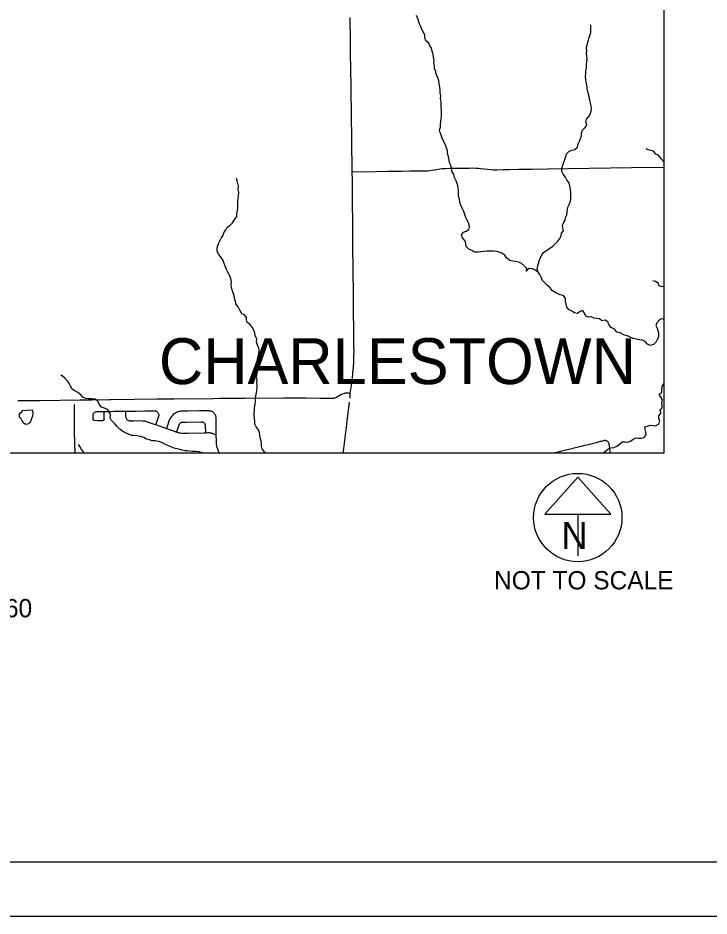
# Model space of a CAD drawing. Extents: x 0 to 34, y 0 to 22.
# Drawn here: x 12.67 to 19.09, y 0 to 8.34 of the extents above; entities that cross this region are included whole.
import ezdxf

# ---------------------------------------------------------------- set-up
doc = ezdxf.new("R2010")
doc.units = 0
for name, color, linetype in [('GM_X_County_Road', 7, 'Continuous'), ('GM_X_Minor_Lake', 7, 'Continuous'), ('GM_X_Minor_River', 7, 'Continuous'), ('GM_X_Township_Road', 7, 'Continuous'), ('GM_X_Township_Text', 7, 'Continuous'), ('SH_Border', 7, 'Continuous'), ('SH_Cut_Line', 7, 'Continuous'), ('SH_Masking', 7, 'Continuous'), ('SH_Text', 7, 'Continuous')]:
    doc.layers.add(name, color=color, linetype=linetype)

msp = doc.modelspace()

# ---------------------------------------------------------------- linework, layer by layer
at = {"layer": 'GM_X_County_Road'}
msp.add_lwpolyline([(15.6909, 4.2991), (15.6957, 4.3413), (15.7237, 4.5646), (15.727, 4.5955), (15.7482, 4.7727)], dxfattribs=at)
at = {"layer": 'GM_X_Minor_Lake'}
msp.add_line((12.805, 4.6981), (12.7056, 4.6922), dxfattribs=at)
msp.add_lwpolyline([(12.7056, 4.6922), (12.7048, 4.6799), (12.6917, 4.6693), (12.6794, 4.6663), (12.6785, 4.6606), (12.6797, 4.6368), (12.6912, 4.6256), (12.7047, 4.603), (12.7173, 4.5832), (12.7411, 4.5692), (12.76, 4.5713), (12.7807, 4.5839), (12.7899, 4.604), (12.801, 4.6288), (12.8084, 4.6497), (12.8092, 4.6602), (12.81, 4.6735), (12.806, 4.6905), (12.805, 4.6981)], dxfattribs=at)
at = {"layer": 'GM_X_Minor_River'}
msp.add_line((18.6636, 5.5436), (18.6712, 5.5421), dxfattribs=at)
for points in [[(16.7712, 6.6571), (16.7623, 6.6845), (16.7611, 6.712), (16.7607, 6.7415), (16.7586, 6.7652), (16.7526, 6.7936), (16.7418, 6.8276), (16.7253, 6.8578), (16.7174, 6.8871), (16.701, 6.9173), (16.696, 6.9448), (16.6919, 6.9722), (16.6793, 6.9968), (16.6752, 7.0214), (16.6683, 7.0498), (16.6603, 7.081), (16.6591, 7.1066), (16.6464, 7.1407), (16.6385, 7.1681), (16.624, 7.1954), (16.6104, 7.2247), (16.5997, 7.2512), (16.5928, 7.2777), (16.5849, 7.3022), (16.5941, 7.327), (16.5948, 7.3546), (16.5992, 7.3821), (16.6017, 7.4059), (16.6052, 7.4316), (16.604, 7.4572), (16.6028, 7.4847), (16.6024, 7.5122), (16.6003, 7.5368), (16.5999, 7.5663), (16.5959, 7.5909), (16.5984, 7.6184), (16.5915, 7.644), (16.5921, 7.6715), (16.588, 7.6971), (16.5839, 7.7284), (16.5788, 7.7577), (16.57, 7.787), (16.5555, 7.8153), (16.5523, 7.8428), (16.5397, 7.8712), (16.5384, 7.8968), (16.5324, 7.9242), (16.535, 7.9499), (16.5309, 7.9755), (16.5259, 8.0029), (16.517, 8.0313), (16.5101, 8.0587), (16.4966, 8.0833), (16.4859, 8.1078), (16.4591, 8.1293), (16.4493, 8.1586), (16.4499, 8.1871), (16.4345, 8.2116), (16.4181, 8.2408), (16.4093, 8.2664), (16.3976, 8.2937), (16.3868, 8.3268), (16.3731, 8.3637)], [(17.5012, 5.9812), (17.4923, 6.0086), (17.4996, 6.0372), (17.5104, 6.0848), (17.5196, 6.1086), (17.5373, 6.1392), (17.5531, 6.1631), (17.5841, 6.1834), (17.6085, 6.2008), (17.6386, 6.2201), (17.6601, 6.2441), (17.6845, 6.2662), (17.7032, 6.2921), (17.7161, 6.3169), (17.7206, 6.3407), (17.7393, 6.3646), (17.7305, 6.3892), (17.7283, 6.4129), (17.7375, 6.4377), (17.7543, 6.4616), (17.7559, 6.4863), (17.7698, 6.5112), (17.7733, 6.5416), (17.7739, 6.5653), (17.7803, 6.5891), (17.7942, 6.6149), (17.8015, 6.6397), (17.805, 6.6663), (17.8075, 6.6986), (17.8053, 6.7251), (17.8031, 6.7488), (17.7971, 6.782), (17.7863, 6.8113), (17.7699, 6.8377), (17.7554, 6.8631), (17.7353, 6.8895), (17.7217, 6.9149), (17.7214, 6.9434), (17.7324, 6.9739), (17.7397, 7.0015), (17.7517, 7.0273), (17.7609, 7.053), (17.7672, 7.0797), (17.7915, 7.1037), (17.818, 7.1116), (17.8425, 7.1185), (17.8688, 7.1416), (17.8741, 7.172), (17.8871, 7.1959), (17.8972, 7.2207), (17.9045, 7.2455), (17.9052, 7.2701), (17.9143, 7.2978), (17.9377, 7.3227), (17.9535, 7.3495), (17.9466, 7.376), (17.9511, 7.3998), (17.9726, 7.4247), (17.9846, 7.4485), (17.9938, 7.4743), (17.9992, 7.499), (17.9941, 7.5246), (17.9882, 7.5492), (17.9822, 7.5785), (17.9752, 7.6088), (17.9692, 7.6372), (17.9613, 7.6666), (17.9582, 7.6903), (17.9532, 7.7168), (17.9491, 7.7433), (17.9459, 7.7689), (17.9437, 7.7964), (17.9453, 7.8211), (17.9469, 7.8505), (17.9504, 7.8781), (17.9529, 7.9047), (17.9535, 7.9332), (17.957, 7.9588), (17.9558, 7.9844), (17.9527, 8.0081), (17.9543, 8.0357), (17.9511, 8.0632), (17.9611, 8.1022), (17.9675, 8.126), (17.9719, 8.1498), (17.9839, 8.1774), (17.9912, 8.205), (17.9909, 8.2288), (17.9925, 8.2534), (17.9913, 8.2781)], [(18.6397, 7.0414), (18.6195, 7.0668), (18.5948, 7.0769), (18.5746, 7.1023), (18.5499, 7.1096), (18.5242, 7.1169), (18.5071, 7.1253)], [(18.6712, 7.0055), (18.6618, 7.0174), (18.6468, 7.0321), (18.6397, 7.0414)], [(14.6845, 6.4724), (14.7013, 6.4972), (14.701, 6.5229), (14.7073, 6.5533), (14.7117, 6.5818), (14.7103, 6.6169), (14.7119, 6.6407), (14.7155, 6.6654), (14.7171, 6.6901), (14.7215, 6.7215), (14.7145, 6.747), (14.717, 6.7774), (14.713, 6.8021), (14.707, 6.8276), (14.6992, 6.8484)], [(18.6636, 5.5436), (18.6499, 5.5473), (18.6291, 5.5377), (18.6066, 5.5099), (18.5956, 5.4851), (18.6091, 5.4597), (18.6189, 5.4332), (18.621, 5.4095), (18.6204, 5.3819), (18.6112, 5.3572), (18.5992, 5.3314), (18.5729, 5.3093), (18.5446, 5.2975), (18.518, 5.3096), (18.4959, 5.3359), (18.4721, 5.348), (18.4437, 5.3514), (18.4143, 5.3568), (18.3867, 5.365), (18.3629, 5.3733), (18.3372, 5.3853), (18.2973, 5.3972), (18.2649, 5.4158), (18.2336, 5.424), (18.2106, 5.4493), (18.182, 5.4661), (18.1599, 5.4943), (18.1483, 5.5198), (18.1244, 5.5347), (18.0952, 5.5277), (18.0713, 5.5464), (18.0476, 5.549), (18.022, 5.5535), (17.9963, 5.5655), (17.9708, 5.5614), (17.946, 5.5725), (17.9315, 5.598), (17.9161, 5.6225), (17.8916, 5.6156), (17.8672, 5.5972), (17.8415, 5.6036), (17.8139, 5.6175), (17.7891, 5.6305), (17.7699, 5.655), (17.7639, 5.6824), (17.7579, 5.7108), (17.7558, 5.7345), (17.7365, 5.7618), (17.7081, 5.7682), (17.6843, 5.7774), (17.6567, 5.7932), (17.6328, 5.8081), (17.6136, 5.8335), (17.5887, 5.856), (17.5629, 5.8813), (17.5408, 5.9067), (17.5292, 5.9322), (17.5166, 5.9567), (17.5012, 5.9812), (17.4754, 5.998), (17.4488, 6.0119), (17.4128, 6.0125), (17.3894, 5.9885), (17.3957, 6.0123), (17.3756, 6.0367), (17.344, 6.0629), (17.3202, 6.0731), (17.2908, 6.0803), (17.2643, 6.0819), (17.2386, 6.0892), (17.2128, 6.1098), (17.1917, 6.138), (17.165, 6.1577), (17.1393, 6.1669), (17.1146, 6.1723), (17.0852, 6.1748), (17.0294, 6.1741), (17.001, 6.1728), (16.9698, 6.1696), (16.9424, 6.1665), (16.9102, 6.167), (16.8854, 6.181), (16.8587, 6.194), (16.8338, 6.2193), (16.8288, 6.2458), (16.82, 6.2742), (16.7988, 6.2996), (16.7891, 6.3251), (16.8087, 6.35), (16.8332, 6.3617), (16.8576, 6.3772), (16.8649, 6.401), (16.858, 6.4303), (16.8415, 6.4633), (16.8289, 6.4879), (16.8201, 6.5162), (16.8113, 6.5427), (16.7967, 6.5748), (16.785, 6.6013), (16.7734, 6.6268), (16.7712, 6.6571)], [(14.6792, 5.7614), (14.6675, 5.7878), (14.6597, 5.8152), (14.6528, 5.8398), (14.6496, 5.8654), (14.6522, 5.8901), (14.6472, 5.9176), (14.6383, 5.945), (14.6229, 5.9743), (14.6064, 6.0035), (14.5947, 6.0356), (14.5849, 6.0612), (14.5761, 6.0886), (14.5597, 6.114), (14.5348, 6.1441), (14.5203, 6.1715), (14.5191, 6.1952), (14.5235, 6.219), (14.5317, 6.2466), (14.5447, 6.2705), (14.5558, 6.2943), (14.5717, 6.3182), (14.5818, 6.3459), (14.6013, 6.3727), (14.6124, 6.3975), (14.6378, 6.413), (14.6621, 6.4389), (14.6836, 6.4714), (14.6845, 6.4724)], [(18.6712, 5.8483), (18.6522, 5.8437), (18.6265, 5.8519), (18.6167, 5.8784), (18.592, 5.8933), (18.5682, 5.8987), (18.5673, 5.8987)], [(14.9681, 4.2991), (14.9557, 4.3141), (14.9394, 4.3386), (14.9325, 4.3641), (14.9322, 4.3879), (14.9272, 4.4125), (14.9202, 4.4409), (14.9152, 4.4655), (14.913, 4.4921), (14.9024, 4.5166), (14.8822, 4.542), (14.8687, 4.5666), (14.8684, 4.5931), (14.8662, 4.6206), (14.8649, 4.6462), (14.8647, 4.6709), (14.8663, 4.6966), (14.8679, 4.7203), (14.8732, 4.7546), (14.8758, 4.7793), (14.8773, 4.8068), (14.8799, 4.8325), (14.8843, 4.8591), (14.8897, 4.8848), (14.8904, 4.9085), (14.892, 4.9342), (14.8889, 4.9588), (14.8924, 4.9836), (14.8855, 5.0091), (14.8927, 5.0396), (14.8934, 5.0643), (14.8978, 5.0918), (14.8956, 5.1184), (14.8934, 5.1459), (14.896, 5.1706), (14.8995, 5.1991), (14.9077, 5.2249), (14.9093, 5.2505), (14.9081, 5.2742), (14.8936, 5.3016), (14.8857, 5.33), (14.8882, 5.3604), (14.8737, 5.3896), (14.8686, 5.4171), (14.8608, 5.4426), (14.8463, 5.4681), (14.8223, 5.4972), (14.7985, 5.5112), (14.7925, 5.5358), (14.7922, 5.5595), (14.7749, 5.585), (14.7483, 5.5942), (14.7299, 5.6281), (14.7135, 5.6573), (14.6943, 5.6846), (14.6892, 5.7102), (14.6805, 5.7348), (14.6792, 5.7614)], [(14.4018, 4.2991), (14.3991, 4.3), (14.3726, 4.3054), (14.345, 4.3117), (14.3147, 4.3142), (14.2901, 4.3139), (14.2446, 4.321), (14.22, 4.3207), (14.1905, 4.328), (14.163, 4.3352), (14.1307, 4.3425), (14.0993, 4.3544), (14.0661, 4.3654), (14.0404, 4.3794), (14.0118, 4.3942), (13.9785, 4.4081), (13.9444, 4.4124), (13.9169, 4.414), (13.8903, 4.4222), (13.8637, 4.4276), (13.838, 4.4444), (13.8085, 4.4545), (13.781, 4.4608), (13.7478, 4.4623), (13.7232, 4.464), (13.6956, 4.475), (13.6671, 4.4861), (13.6413, 4.5019), (13.6165, 4.5206), (13.5916, 4.545), (13.5676, 4.5713), (13.537, 4.6023), (13.5263, 4.6268), (13.5298, 4.6525), (13.5191, 4.6771), (13.5018, 4.7034), (13.4714, 4.7154), (13.4438, 4.7265), (13.4245, 4.7528), (13.4119, 4.7802), (13.3852, 4.7989), (13.3587, 4.8024), (13.3255, 4.8029), (13.299, 4.8074), (13.2714, 4.8184), (13.2503, 4.8438), (13.2264, 4.8635), (13.1987, 4.8783), (13.1721, 4.8942), (13.1576, 4.9206), (13.144, 4.9451), (13.1276, 4.9705), (13.1056, 4.9959), (13.0798, 5.0155), (13.0665, 5.0239)], [(18.6366, 4.6939), (18.6533, 4.7188), (18.6531, 4.7434), (18.6509, 4.7691), (18.6572, 4.7929), (18.6427, 4.8193), (18.6264, 4.8438), (18.6517, 4.8668), (18.6524, 4.8915), (18.6558, 4.9172), (18.6707, 4.944), (18.6712, 4.9453)], [(18.1036, 4.2991), (18.1266, 4.3177), (18.151, 4.337), (18.1783, 4.3478), (18.2067, 4.3528), (18.234, 4.3636), (18.2594, 4.3829), (18.2838, 4.4041), (18.3093, 4.4053), (18.334, 4.4018), (18.3604, 4.4106), (18.3848, 4.4299), (18.4093, 4.4406), (18.433, 4.439), (18.4586, 4.4374), (18.4859, 4.4444), (18.5056, 4.4683), (18.5034, 4.4949), (18.4965, 4.5195), (18.4934, 4.5441), (18.5179, 4.5482), (18.5434, 4.559), (18.5699, 4.5555), (18.5936, 4.5519), (18.62, 4.5674), (18.633, 4.5923), (18.6222, 4.6197), (18.6238, 4.6453), (18.6444, 4.6693), (18.6366, 4.6939)], [(13.2844, 4.2991), (13.2808, 4.3088), (13.2597, 4.3342), (13.2433, 4.3596), (13.2327, 4.3804)]]:
    msp.add_lwpolyline(points, dxfattribs=at)
at = {"layer": 'GM_X_Township_Road'}
for points in [[(15.7571, 4.8533), (15.7626, 4.8939), (15.7649, 4.9108), (15.7676, 4.9307), (15.7727, 4.9708), (15.7747, 4.9862), (15.776, 4.9969), (15.7769, 5.0046), (15.7796, 5.0277), (15.7804, 5.0354), (15.7816, 5.0477), (15.7838, 5.0693), (15.7843, 5.0755), (15.7852, 5.0862), (15.7865, 5.1033), (15.7888, 5.1389), (15.7892, 5.1497), (15.7895, 5.1575), (15.79, 5.173), (15.791, 5.2087), (15.7914, 5.2475), (15.7909, 5.2862), (15.7903, 5.3203), (15.7902, 5.3342), (15.79, 5.3528), (15.7897, 5.3745), (15.7896, 5.3916), (15.7895, 5.407), (15.7893, 5.4302), (15.7891, 5.4458), (15.7888, 5.4768), (15.7887, 5.4907), (15.7886, 5.5062), (15.7879, 5.5527), (15.7878, 5.5651), (15.7875, 5.5806), (15.7874, 5.593), (15.7873, 5.6116), (15.7872, 5.6271), (15.7871, 5.6348), (15.7869, 5.6519), (15.7867, 5.6845), (15.7866, 5.7031), (15.7865, 5.7326), (15.7863, 5.7606), (15.786, 5.7792), (15.7856, 5.818), (15.7852, 5.8475), (15.7852, 5.8581), (15.7852, 5.8781), (15.7847, 5.8982), (15.7845, 5.9197), (15.7843, 5.941), (15.7837, 6), (15.7833, 6.0264), (15.7832, 6.0419), (15.7817, 6.1802), (15.781, 6.2625), (15.7804, 6.3309), (15.7803, 6.3791), (15.7802, 6.3884), (15.7801, 6.4054), (15.7799, 6.4163), (15.7799, 6.424), (15.7793, 6.4566), (15.7791, 6.4721), (15.779, 6.4892), (15.7789, 6.5016), (15.7789, 6.5109), (15.7786, 6.5512), (15.7787, 6.559), (15.7785, 6.573), (15.7782, 6.5869), (15.778, 6.5946), (15.7779, 6.6039), (15.7769, 6.7746), (15.7759, 6.8289), (15.7749, 6.9115), (15.7738, 6.9977), (15.7723, 7.1237), (15.7704, 7.2496), (15.7675, 7.4112), (15.7641, 7.7082), (15.7597, 8.0144), (15.7581, 8.1139), (15.7548, 8.3455)], [(15.7749, 6.9115), (15.9949, 6.9154), (16.1068, 6.9167), (16.2296, 6.9182), (16.3166, 6.9195), (16.4083, 6.9204), (16.4518, 6.921), (16.4766, 6.9223), (16.4952, 6.9241), (16.5183, 6.9271), (16.5597, 6.9341), (16.5873, 6.9385), (16.6089, 6.9411), (16.643, 6.9432), (16.6819, 6.9442), (16.7906, 6.9454), (16.8652, 6.9471), (16.8948, 6.9475), (16.9258, 6.9468), (16.9444, 6.9457), (16.9676, 6.9435), (17.0339, 6.9352), (17.0617, 6.9327), (17.0834, 6.9317), (17.1223, 6.9314), (17.1766, 6.9321), (17.2357, 6.9332), (17.3211, 6.9349), (17.447, 6.9372), (17.5883, 6.9391), (18.3682, 6.9507), (18.6712, 6.9546)], [(15.7571, 4.8533), (15.7413, 4.8545), (15.7336, 4.8551), (15.7212, 4.8552), (15.712, 4.8545), (15.7062, 4.8537), (15.7012, 4.8528), (15.6893, 4.8494), (15.6763, 4.8442), (15.671, 4.8417), (15.6666, 4.8393), (15.6439, 4.8257), (15.6276, 4.8171), (15.6189, 4.8134), (15.6097, 4.81), (15.6032, 4.808), (15.5984, 4.807), (15.5928, 4.8064), (15.5796, 4.8051), (15.4775, 4.8064), (15.346, 4.8084), (15.1371, 4.8085), (14.7726, 4.8064), (14.6775, 4.8063), (14.6418, 4.8061), (14.5424, 4.8052), (14.485, 4.8047), (14.1199, 4.8018), (13.963, 4.8001), (13.5359, 4.7941), (13.5157, 4.794), (13.3548, 4.7916), (13.2464, 4.7916), (12.8744, 4.7863), (12.6682, 4.7848)], [(15.7558, 4.811), (15.7548, 4.8134), (15.7544, 4.8157), (15.7541, 4.8179), (15.754, 4.8201), (15.754, 4.8256), (15.7544, 4.8317), (15.7557, 4.8432), (15.7571, 4.8533)], [(13.1988, 4.2991), (13.1984, 4.3816), (13.1951, 4.5105), (13.1937, 4.5756), (13.1934, 4.6353), (13.1936, 4.687), (13.1937, 4.7102), (13.1935, 4.7288), (13.1932, 4.7459), (13.1932, 4.7521)], [(13.4699, 4.6148), (13.4694, 4.6114), (13.4688, 4.61), (13.467, 4.6075), (13.4653, 4.6059), (13.4635, 4.6046), (13.4608, 4.603), (13.4574, 4.6014), (13.4538, 4.6001), (13.4505, 4.5993), (13.4466, 4.5984), (13.4429, 4.5978), (13.4389, 4.5976), (13.4352, 4.5976), (13.4089, 4.5999), (13.384, 4.6016), (13.3779, 4.6025), (13.3752, 4.6033), (13.3735, 4.604), (13.3709, 4.6057), (13.3696, 4.6069), (13.3679, 4.6094), (13.367, 4.6119), (13.3668, 4.6137), (13.3665, 4.6262), (13.3666, 4.6417), (13.3668, 4.6491), (13.3675, 4.6557), (13.3685, 4.6599), (13.3698, 4.6632), (13.3716, 4.6662), (13.3736, 4.6695), (13.3769, 4.6733), (13.3804, 4.6767), (13.3844, 4.6796), (13.3884, 4.6818), (13.3929, 4.6832), (13.3964, 4.684), (13.4021, 4.6847), (13.4079, 4.6853), (13.4176, 4.6857), (13.4685, 4.686), (13.4766, 4.686), (13.5356, 4.6869), (13.562, 4.6874), (13.6225, 4.6883), (13.6683, 4.6888), (13.767, 4.6897), (13.8478, 4.6911), (13.9161, 4.6916), (13.9349, 4.6915), (13.9393, 4.6914), (13.9424, 4.6912), (13.9455, 4.6906), (13.9491, 4.6896), (13.953, 4.6883), (13.9585, 4.6856), (13.961, 4.6838), (13.9635, 4.6818), (13.9678, 4.6774), (13.9721, 4.6709), (13.9749, 4.6654), (13.976, 4.6622), (13.9765, 4.6594), (13.977, 4.6564), (13.9774, 4.6517), (13.9774, 4.6487), (13.9771, 4.6455), (13.9756, 4.6395), (13.9601, 4.5955), (13.9534, 4.5783), (13.9479, 4.5638)], [(13.4699, 4.6148), (13.4685, 4.6707), (13.4685, 4.6738), (13.4685, 4.686)], [(13.6683, 4.6888), (13.6684, 4.6805), (13.6687, 4.6601), (13.6687, 4.6506), (13.669, 4.6422), (13.6695, 4.6378), (13.6702, 4.6325), (13.671, 4.6289), (13.6733, 4.6238), (13.6769, 4.6175), (13.6804, 4.6129), (13.6847, 4.6089), (13.6895, 4.6056), (13.6948, 4.6031), (13.6979, 4.6019), (13.7018, 4.601), (13.7042, 4.6006), (13.7092, 4.6001), (13.7246, 4.6), (13.7448, 4.6001), (13.7929, 4.6008), (13.8272, 4.6006), (13.8314, 4.6004), (13.836, 4.6001), (13.8411, 4.5992), (13.8461, 4.598), (13.8611, 4.5935), (13.9332, 4.5688), (13.9479, 4.5638), (14.0008, 4.5457), (14.0499, 4.5281), (14.0959, 4.5116), (14.1441, 4.4949), (14.1515, 4.4923), (14.1648, 4.4887), (14.1753, 4.4869), (14.189, 4.4856), (14.2121, 4.4851), (14.2509, 4.4857), (14.3999, 4.4887), (14.41, 4.489), (14.4295, 4.4897), (14.4452, 4.4894), (14.4562, 4.4882), (14.4655, 4.4862), (14.4687, 4.4854), (14.4731, 4.4837), (14.4804, 4.4803), (14.4923, 4.475), (14.5029, 4.4713), (14.5115, 4.4689)], [(14.5417, 4.2991), (14.5329, 4.3175), (14.5258, 4.3345), (14.5202, 4.352), (14.5164, 4.3684), (14.5145, 4.3804), (14.5135, 4.3911), (14.5127, 4.4142), (14.5115, 4.4689), (14.5114, 4.5133), (14.5108, 4.5894), (14.5108, 4.5955), (14.5109, 4.6157), (14.5107, 4.6218), (14.5103, 4.6284), (14.5096, 4.6345), (14.5087, 4.6394), (14.5075, 4.6444), (14.5062, 4.6485), (14.5049, 4.6519), (14.5032, 4.6558), (14.5016, 4.6582), (14.4988, 4.6625), (14.4964, 4.6659), (14.4922, 4.6708), (14.4861, 4.6762), (14.4782, 4.6816), (14.4712, 4.6854), (14.4669, 4.6872), (14.4636, 4.6882), (14.4558, 4.6901), (14.4478, 4.6911), (14.4349, 4.6915), (14.4166, 4.6918), (14.384, 4.6913), (14.3545, 4.691), (14.2474, 4.6891), (14.2195, 4.6885), (14.1915, 4.688), (14.1841, 4.6875), (14.1773, 4.6868), (14.1667, 4.685), (14.1604, 4.6832), (14.1542, 4.6813), (14.1425, 4.6764), (14.1314, 4.6705), (14.1208, 4.6637), (14.1121, 4.6568), (14.1018, 4.647), (14.0945, 4.6386), (14.0881, 4.6296), (14.081, 4.6173), (14.0748, 4.6046), (14.0681, 4.5871), (14.0611, 4.5663), (14.0528, 4.538), (14.0499, 4.5281)], [(14.1441, 4.4949), (14.1463, 4.5011), (14.1704, 4.5677), (14.173, 4.5733), (14.1743, 4.5755), (14.1757, 4.5772), (14.179, 4.5804), (14.1814, 4.5823), (14.1839, 4.5839), (14.1865, 4.5851), (14.189, 4.5861), (14.1929, 4.587), (14.1968, 4.5875), (14.2332, 4.5882), (14.3714, 4.5893), (14.3807, 4.5891), (14.383, 4.5889), (14.3852, 4.5884), (14.3874, 4.5877), (14.3896, 4.5869), (14.3937, 4.5846), (14.3974, 4.5818), (14.3994, 4.5798), (14.4016, 4.5772), (14.405, 4.572), (14.4062, 4.5694), (14.4076, 4.5664), (14.4085, 4.5634), (14.4091, 4.5588), (14.4096, 4.5541), (14.4097, 4.5391), (14.4099, 4.5077), (14.41, 4.489)], [(18.1715, 4.2991), (18.1706, 4.3053), (18.1673, 4.3424), (18.1656, 4.361), (18.1648, 4.3703), (18.1637, 4.3779), (18.1628, 4.3828), (18.1616, 4.387), (18.1591, 4.3926), (18.1567, 4.3966), (18.1518, 4.4026), (18.1472, 4.4068), (18.1421, 4.4104), (18.1366, 4.4132), (18.1323, 4.4147), (18.1284, 4.4154), (18.1246, 4.4156), (18.1169, 4.415), (18.1108, 4.4142), (18.0956, 4.4106), (18.0867, 4.4083), (18.0792, 4.4063), (18.0672, 4.4032), (18.0402, 4.3962), (17.9664, 4.3776), (17.9543, 4.3746), (17.9316, 4.3691), (17.9, 4.3613), (17.8849, 4.3576), (17.8608, 4.3515), (17.8338, 4.3447), (17.8173, 4.3405), (17.7992, 4.336), (17.7631, 4.327), (17.7495, 4.3236), (17.7375, 4.3207), (17.7193, 4.3165), (17.6891, 4.3095), (17.671, 4.3052), (17.6619, 4.3032), (17.6449, 4.2991)]]:
    msp.add_lwpolyline(points, dxfattribs=at)
at = {"layer": 'SH_Border'}
msp.add_lwpolyline([(1.5, 21.5), (33.5, 21.5), (33.5, 0.5), (1.5, 0.5)], close=True, dxfattribs=at)
at = {"layer": 'SH_Cut_Line'}
msp.add_lwpolyline([(0, 0), (34, 0), (34, 22), (0, 22)], close=True, dxfattribs=at)
at = {"layer": 'SH_Masking'}
msp.add_circle((17.8706, 3.7009), 0.41, dxfattribs=at)
at = {"layer": 'SH_Text'}
for p, q in [((17.8706, 4.0747), (17.563, 3.7335)), ((18.1782, 3.7335), (17.8706, 4.0747)), ((17.563, 3.7335), (18.1782, 3.7335)), ((17.8706, 3.7335), (17.8706, 3.3467))]:
    msp.add_line(p, q, dxfattribs=at)
msp.add_lwpolyline([(1.6712, 21.2991), (18.6712, 21.2991), (18.6712, 4.2991), (1.6712, 4.2991)], close=True, dxfattribs=at)
msp.add_circle((17.8706, 3.7009), 0.41, dxfattribs=at)

# ---------------------------------------------------------------- texts
at = {"layer": 'GM_X_Township_Text'}
msp.add_text('CHARLESTOWN', height=0.426136, rotation=0.00001, dxfattribs=at).set_placement((13.9786, 4.9402))
at = {"layer": 'SH_Text'}
for s, height, p in [('N', 0.25, (17.7193, 3.4096)), ('NOT TO SCALE', 0.17, (17.0927, 3.0337)), ('CLOSE STRUCTURE POR-44-17.02 PER STANDARD CONSTRUCTION DRAWING MT-101.60', 0.17, (2.9732, 2.7744))]:
    msp.add_text(s, height=height, dxfattribs=at).set_placement(p)

doc.saveas('drawing.dxf')
